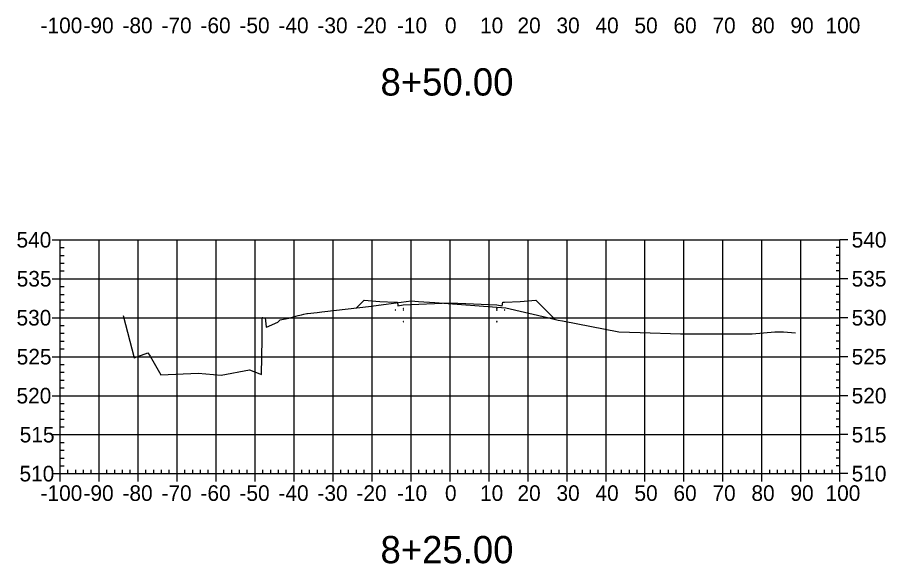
# Model space of a CAD drawing. Extents: x 708103 to 717568, y 374476 to 378707.
# Drawn here: x 716520.5 to 716743.2, y 376405 to 376545.1 of the extents above; entities that cross this region are included whole.
import ezdxf

# ---------------------------------------------------------------- set-up
doc = ezdxf.new("R2010")
doc.units = 0
for name, color, linetype in [('1', 7, 'Continuous'), ('14', 7, 'Continuous'), ('22', 7, 'Continuous'), ('57', 7, 'Continuous'), ('Existing', 7, 'Continuous')]:
    doc.layers.add(name, color=color, linetype=linetype)

msp = doc.modelspace()

# ---------------------------------------------------------------- linework, layer by layer
for points in [[(716617.45, 376470.02), (716617.55, 376470.02), (716617.55, 376470.12), (716617.45, 376470.12)], [(716619.45, 376470.36), (716619.55, 376470.36), (716619.55, 376470.46), (716619.45, 376470.46)], [(716619.45, 376470.02), (716619.55, 376470.02), (716619.55, 376470.12), (716619.45, 376470.12)], [(716631.45, 376470.5), (716631.55, 376470.5), (716631.55, 376470.6), (716631.45, 376470.6)], [(716643.45, 376470.36), (716643.55, 376470.36), (716643.55, 376470.46), (716643.45, 376470.46)], [(716643.45, 376470.02), (716643.55, 376470.02), (716643.55, 376470.12), (716643.45, 376470.12)], [(716645.45, 376470.02), (716645.55, 376470.02), (716645.55, 376470.12), (716645.45, 376470.12)], [(716631.45, 376467.5), (716631.55, 376467.5), (716631.55, 376467.6), (716631.45, 376467.6)], [(716619.45, 376467.02), (716619.55, 376467.02), (716619.55, 376467.12), (716619.45, 376467.12)], [(716643.45, 376467.02), (716643.55, 376467.02), (716643.55, 376467.12), (716643.45, 376467.12)]]:
    msp.add_lwpolyline(points, close=True)
at = {"layer": '14'}
for points in [[(716607.55, 376470.6), (716607.55, 376470.65), (716607.55, 376470.6), (716607.5, 376470.6), (716607.55, 376470.6), (716607.55, 376470.55), (716607.55, 376470.6), (716607.6, 376470.6)], [(716658.37, 376467.68), (716658.37, 376467.73), (716658.37, 376467.68), (716658.32, 376467.68), (716658.37, 376467.68), (716658.37, 376467.63), (716658.37, 376467.68), (716658.42, 376467.68)]]:
    msp.add_lwpolyline(points, dxfattribs=at)
at = {"layer": '22'}
msp.add_lwpolyline([(716607.55, 376470.6), (716609.5, 376472.55), (716613.5, 376472.23), (716617.5, 376472.07), (716618, 376472.07), (716618.08, 376471.16), (716619.5, 376471.41), (716631.5, 376471.89), (716643.5, 376471.41), (716644.91, 376471.16), (716645, 376472.07), (716645.5, 376472.07), (716649.5, 376472.23), (716653.5, 376472.55), (716658.37, 376467.68)], dxfattribs=at)
at = {"layer": '57'}
for p, q in [((716529.5, 376488.07), (716531.5, 376488.07)), ((716531.5, 376488.07), (716731.5, 376488.07)), ((716531.5, 376428.07), (716531.5, 376488.07)), ((716531.5, 376428.07), (716531.5, 376488.07)), ((716541.5, 376428.07), (716541.5, 376488.07)), ((716551.5, 376428.07), (716551.5, 376488.07)), ((716561.5, 376428.07), (716561.5, 376488.07)), ((716571.5, 376428.07), (716571.5, 376488.07)), ((716581.5, 376428.07), (716581.5, 376488.07)), ((716591.5, 376428.07), (716591.5, 376488.07)), ((716601.5, 376428.07), (716601.5, 376488.07)), ((716611.5, 376428.07), (716611.5, 376488.07)), ((716621.5, 376428.07), (716621.5, 376488.07)), ((716631.5, 376428.07), (716631.5, 376488.07)), ((716641.5, 376428.07), (716641.5, 376488.07)), ((716651.5, 376428.07), (716651.5, 376488.07)), ((716661.5, 376428.07), (716661.5, 376488.07)), ((716671.5, 376428.07), (716671.5, 376488.07)), ((716681.5, 376428.07), (716681.5, 376488.07)), ((716691.5, 376428.07), (716691.5, 376488.07)), ((716701.5, 376428.07), (716701.5, 376488.07)), ((716711.5, 376428.07), (716711.5, 376488.07)), ((716721.5, 376428.07), (716721.5, 376488.07)), ((716731.5, 376428.07), (716731.5, 376488.07)), ((716731.5, 376428.07), (716731.5, 376488.07)), ((716733.5, 376488.07), (716731.5, 376488.07)), ((716531.5, 376486.07), (716532.5, 376486.07)), ((716731.5, 376486.07), (716730.5, 376486.07)), ((716531.5, 376484.07), (716532.5, 376484.07)), ((716731.5, 376484.07), (716730.5, 376484.07)), ((716531.5, 376482.07), (716532.5, 376482.07)), ((716731.5, 376482.07), (716730.5, 376482.07)), ((716531.5, 376480.07), (716532.5, 376480.07)), ((716731.5, 376480.07), (716730.5, 376480.07)), ((716529.5, 376478.07), (716531.5, 376478.07)), ((716531.5, 376478.07), (716731.5, 376478.07)), ((716733.5, 376478.07), (716731.5, 376478.07)), ((716531.5, 376476.07), (716532.5, 376476.07)), ((716531.5, 376474.07), (716532.5, 376474.07)), ((716731.5, 376476.07), (716730.5, 376476.07)), ((716731.5, 376474.07), (716730.5, 376474.07)), ((716531.5, 376472.07), (716532.5, 376472.07)), ((716731.5, 376472.07), (716730.5, 376472.07)), ((716531.5, 376470.07), (716532.5, 376470.07)), ((716731.5, 376470.07), (716730.5, 376470.07)), ((716529.5, 376468.07), (716531.5, 376468.07)), ((716531.5, 376468.07), (716731.5, 376468.07)), ((716733.5, 376468.07), (716731.5, 376468.07)), ((716531.5, 376466.07), (716532.5, 376466.07)), ((716731.5, 376466.07), (716730.5, 376466.07)), ((716531.5, 376464.07), (716532.5, 376464.07)), ((716731.5, 376464.07), (716730.5, 376464.07)), ((716531.5, 376462.07), (716532.5, 376462.07)), ((716731.5, 376462.07), (716730.5, 376462.07)), ((716531.5, 376460.07), (716532.5, 376460.07)), ((716731.5, 376460.07), (716730.5, 376460.07)), ((716529.5, 376458.07), (716531.5, 376458.07)), ((716531.5, 376458.07), (716731.5, 376458.07)), ((716733.5, 376458.07), (716731.5, 376458.07)), ((716531.5, 376456.07), (716532.5, 376456.07)), ((716531.5, 376454.07), (716532.5, 376454.07)), ((716731.5, 376456.07), (716730.5, 376456.07)), ((716731.5, 376454.07), (716730.5, 376454.07)), ((716531.5, 376452.07), (716532.5, 376452.07)), ((716731.5, 376452.07), (716730.5, 376452.07)), ((716531.5, 376450.07), (716532.5, 376450.07)), ((716731.5, 376450.07), (716730.5, 376450.07)), ((716529.5, 376448.07), (716531.5, 376448.07)), ((716531.5, 376448.07), (716731.5, 376448.07)), ((716733.5, 376448.07), (716731.5, 376448.07)), ((716531.5, 376446.07), (716532.5, 376446.07)), ((716731.5, 376446.07), (716730.5, 376446.07)), ((716531.5, 376444.07), (716532.5, 376444.07)), ((716731.5, 376444.07), (716730.5, 376444.07)), ((716531.5, 376442.07), (716532.5, 376442.07)), ((716731.5, 376442.07), (716730.5, 376442.07)), ((716531.5, 376440.07), (716532.5, 376440.07)), ((716731.5, 376440.07), (716730.5, 376440.07)), ((716529.5, 376438.07), (716531.5, 376438.07)), ((716531.5, 376438.07), (716731.5, 376438.07)), ((716733.5, 376438.07), (716731.5, 376438.07)), ((716531.5, 376436.07), (716532.5, 376436.07)), ((716531.5, 376434.07), (716532.5, 376434.07)), ((716731.5, 376436.07), (716730.5, 376436.07)), ((716731.5, 376434.07), (716730.5, 376434.07)), ((716531.5, 376432.07), (716532.5, 376432.07)), ((716731.5, 376432.07), (716730.5, 376432.07)), ((716531.5, 376430.07), (716532.5, 376430.07)), ((716731.5, 376430.07), (716730.5, 376430.07)), ((716529.5, 376428.07), (716531.5, 376428.07)), ((716531.5, 376428.07), (716731.5, 376428.07)), ((716531.5, 376428.07), (716731.5, 376428.07)), ((716531.5, 376426.07), (716531.5, 376428.07)), ((716533.5, 376428.07), (716533.5, 376429.07)), ((716535.5, 376428.07), (716535.5, 376429.07)), ((716537.5, 376428.07), (716537.5, 376429.07)), ((716539.5, 376428.07), (716539.5, 376429.07)), ((716541.5, 376426.07), (716541.5, 376428.07)), ((716543.5, 376428.07), (716543.5, 376429.07)), ((716545.5, 376428.07), (716545.5, 376429.07)), ((716547.5, 376428.07), (716547.5, 376429.07)), ((716549.5, 376428.07), (716549.5, 376429.07)), ((716551.5, 376426.07), (716551.5, 376428.07)), ((716553.5, 376428.07), (716553.5, 376429.07)), ((716555.5, 376428.07), (716555.5, 376429.07)), ((716557.5, 376428.07), (716557.5, 376429.07)), ((716559.5, 376428.07), (716559.5, 376429.07)), ((716561.5, 376426.07), (716561.5, 376428.07)), ((716563.5, 376428.07), (716563.5, 376429.07)), ((716565.5, 376428.07), (716565.5, 376429.07)), ((716567.5, 376428.07), (716567.5, 376429.07)), ((716569.5, 376428.07), (716569.5, 376429.07)), ((716571.5, 376426.07), (716571.5, 376428.07)), ((716573.5, 376428.07), (716573.5, 376429.07)), ((716575.5, 376428.07), (716575.5, 376429.07)), ((716577.5, 376428.07), (716577.5, 376429.07)), ((716579.5, 376428.07), (716579.5, 376429.07)), ((716581.5, 376426.07), (716581.5, 376428.07)), ((716583.5, 376428.07), (716583.5, 376429.07)), ((716585.5, 376428.07), (716585.5, 376429.07)), ((716587.5, 376428.07), (716587.5, 376429.07)), ((716589.5, 376428.07), (716589.5, 376429.07)), ((716591.5, 376426.07), (716591.5, 376428.07)), ((716593.5, 376428.07), (716593.5, 376429.07)), ((716595.5, 376428.07), (716595.5, 376429.07)), ((716597.5, 376428.07), (716597.5, 376429.07)), ((716599.5, 376428.07), (716599.5, 376429.07)), ((716601.5, 376426.07), (716601.5, 376428.07)), ((716603.5, 376428.07), (716603.5, 376429.07)), ((716605.5, 376428.07), (716605.5, 376429.07)), ((716607.5, 376428.07), (716607.5, 376429.07)), ((716609.5, 376428.07), (716609.5, 376429.07)), ((716611.5, 376426.07), (716611.5, 376428.07)), ((716613.5, 376428.07), (716613.5, 376429.07)), ((716615.5, 376428.07), (716615.5, 376429.07)), ((716617.5, 376428.07), (716617.5, 376429.07)), ((716619.5, 376428.07), (716619.5, 376429.07)), ((716621.5, 376426.07), (716621.5, 376428.07)), ((716623.5, 376428.07), (716623.5, 376429.07)), ((716625.5, 376428.07), (716625.5, 376429.07)), ((716627.5, 376428.07), (716627.5, 376429.07)), ((716629.5, 376428.07), (716629.5, 376429.07)), ((716631.5, 376426.07), (716631.5, 376428.07)), ((716633.5, 376428.07), (716633.5, 376429.07)), ((716635.5, 376428.07), (716635.5, 376429.07)), ((716637.5, 376428.07), (716637.5, 376429.07)), ((716639.5, 376428.07), (716639.5, 376429.07)), ((716641.5, 376426.07), (716641.5, 376428.07)), ((716643.5, 376428.07), (716643.5, 376429.07)), ((716645.5, 376428.07), (716645.5, 376429.07)), ((716647.5, 376428.07), (716647.5, 376429.07)), ((716649.5, 376428.07), (716649.5, 376429.07)), ((716651.5, 376426.07), (716651.5, 376428.07)), ((716653.5, 376428.07), (716653.5, 376429.07)), ((716655.5, 376428.07), (716655.5, 376429.07)), ((716657.5, 376428.07), (716657.5, 376429.07)), ((716659.5, 376428.07), (716659.5, 376429.07)), ((716661.5, 376426.07), (716661.5, 376428.07)), ((716663.5, 376428.07), (716663.5, 376429.07)), ((716665.5, 376428.07), (716665.5, 376429.07)), ((716667.5, 376428.07), (716667.5, 376429.07)), ((716669.5, 376428.07), (716669.5, 376429.07)), ((716671.5, 376426.07), (716671.5, 376428.07)), ((716673.5, 376428.07), (716673.5, 376429.07)), ((716675.5, 376428.07), (716675.5, 376429.07)), ((716677.5, 376428.07), (716677.5, 376429.07)), ((716679.5, 376428.07), (716679.5, 376429.07)), ((716681.5, 376426.07), (716681.5, 376428.07)), ((716683.5, 376428.07), (716683.5, 376429.07)), ((716685.5, 376428.07), (716685.5, 376429.07)), ((716687.5, 376428.07), (716687.5, 376429.07)), ((716689.5, 376428.07), (716689.5, 376429.07)), ((716691.5, 376426.07), (716691.5, 376428.07)), ((716693.5, 376428.07), (716693.5, 376429.07)), ((716695.5, 376428.07), (716695.5, 376429.07)), ((716697.5, 376428.07), (716697.5, 376429.07)), ((716699.5, 376428.07), (716699.5, 376429.07)), ((716701.5, 376426.07), (716701.5, 376428.07)), ((716703.5, 376428.07), (716703.5, 376429.07)), ((716705.5, 376428.07), (716705.5, 376429.07)), ((716707.5, 376428.07), (716707.5, 376429.07)), ((716709.5, 376428.07), (716709.5, 376429.07)), ((716711.5, 376426.07), (716711.5, 376428.07)), ((716713.5, 376428.07), (716713.5, 376429.07)), ((716715.5, 376428.07), (716715.5, 376429.07)), ((716717.5, 376428.07), (716717.5, 376429.07)), ((716719.5, 376428.07), (716719.5, 376429.07)), ((716721.5, 376426.07), (716721.5, 376428.07)), ((716723.5, 376428.07), (716723.5, 376429.07)), ((716725.5, 376428.07), (716725.5, 376429.07)), ((716727.5, 376428.07), (716727.5, 376429.07)), ((716729.5, 376428.07), (716729.5, 376429.07)), ((716731.5, 376426.07), (716731.5, 376428.07)), ((716733.5, 376428.07), (716731.5, 376428.07))]:
    msp.add_line(p, q, dxfattribs=at)
at = {"layer": 'Existing'}
msp.add_lwpolyline([(716547.63, 376468.64), (716550.5, 376457.79), (716554.04, 376459.07), (716554.59, 376458.24), (716557.35, 376453.4), (716566.9, 376453.86), (716572.84, 376453.34), (716580.1, 376454.67), (716582.75, 376453.64), (716583.16, 376453.47), (716583.3, 376462.58), (716583.33, 376468.12), (716583.53, 376468.13), (716584.08, 376468.08), (716584.38, 376465.75), (716584.42, 376465.63), (716587.37, 376466.97), (716587.92, 376467.54), (716590.16, 376467.98), (716592.53, 376468.61), (716593.39, 376468.79), (716594.04, 376469), (716594.8, 376469.14), (716594.9, 376469.16), (716594.98, 376469.17), (716597.46, 376469.42), (716598.63, 376469.54), (716605.38, 376470.35), (716610.62, 376470.97), (716615.13, 376471.52), (716621.53, 376472.4), (716623.39, 376472.25), (716627.61, 376471.97), (716645.8, 376470.65), (716656.5, 376468.13), (716659.19, 376467.48), (716660.33, 376467.28), (716674.78, 376464.42), (716680.23, 376464.25), (716690.62, 376463.9), (716709.02, 376463.95), (716714.83, 376464.42), (716717, 376464.45), (716720.06, 376464.2)], dxfattribs=at)

# ---------------------------------------------------------------- texts
at = {"layer": '1'}
for s, p in [('8+50.00', (716613.67, 376525.07)), ('8+25.00', (716613.67, 376405.07))]:
    msp.add_text(s, height=7, dxfattribs=at).set_placement(p)
at = {"layer": '14'}
for p in [(716613.46, 376472.18), (716649.46, 376472.18), (716613.46, 376471.52), (716617.46, 376471.36), (716645.46, 376471.36), (716649.46, 376471.52)]:
    msp.add_text('+', height=0.1, dxfattribs=at).set_placement(p)
at = {"layer": '57'}
for s, p in [('-100', (716526.49, 376541.07)), ('-90', (716537.5, 376541.07)), ('-80', (716547.5, 376541.07)), ('-70', (716557.5, 376541.07)), ('-60', (716567.5, 376541.07)), ('-50', (716577.5, 376541.07)), ('-40', (716587.5, 376541.07)), ('-30', (716597.5, 376541.07)), ('-20', (716607.5, 376541.07)), ('-10', (716617.88, 376541.07)), ('0', (716630.2, 376541.07)), ('10', (716639.19, 376541.07)), ('20', (716648.8, 376541.07)), ('30', (716658.8, 376541.07)), ('40', (716668.8, 376541.07)), ('50', (716678.8, 376541.07)), ('60', (716688.8, 376541.07)), ('70', (716698.8, 376541.07)), ('80', (716708.8, 376541.07)), ('90', (716718.8, 376541.07)), ('100', (716727.8, 376541.07)), ('540', (716520.32, 376486.07)), ('540', (716734.5, 376486.07)), ('535', (716520.37, 376476.07)), ('535', (716734.5, 376476.07)), ('530', (716520.32, 376466.07)), ('530', (716734.5, 376466.07)), ('525', (716520.37, 376456.07)), ('525', (716734.5, 376456.07)), ('520', (716520.32, 376446.07)), ('520', (716734.5, 376446.07)), ('515', (716521.14, 376436.07)), ('515', (716734.5, 376436.07)), ('510', (716521.09, 376426.07)), ('510', (716734.5, 376426.07)), ('-100', (716526.49, 376421.07)), ('-90', (716537.5, 376421.07)), ('-80', (716547.5, 376421.07)), ('-70', (716557.5, 376421.07)), ('-60', (716567.5, 376421.07)), ('-50', (716577.5, 376421.07)), ('-40', (716587.5, 376421.07)), ('-30', (716597.5, 376421.07)), ('-20', (716607.5, 376421.07)), ('-10', (716617.88, 376421.07)), ('0', (716630.2, 376421.07)), ('10', (716639.19, 376421.07)), ('20', (716648.8, 376421.07)), ('30', (716658.8, 376421.07)), ('40', (716668.8, 376421.07)), ('50', (716678.8, 376421.07)), ('60', (716688.8, 376421.07)), ('70', (716698.8, 376421.07)), ('80', (716708.8, 376421.07)), ('90', (716718.8, 376421.07)), ('100', (716727.8, 376421.07))]:
    msp.add_text(s, height=4, dxfattribs=at).set_placement(p)

doc.saveas('drawing.dxf')
